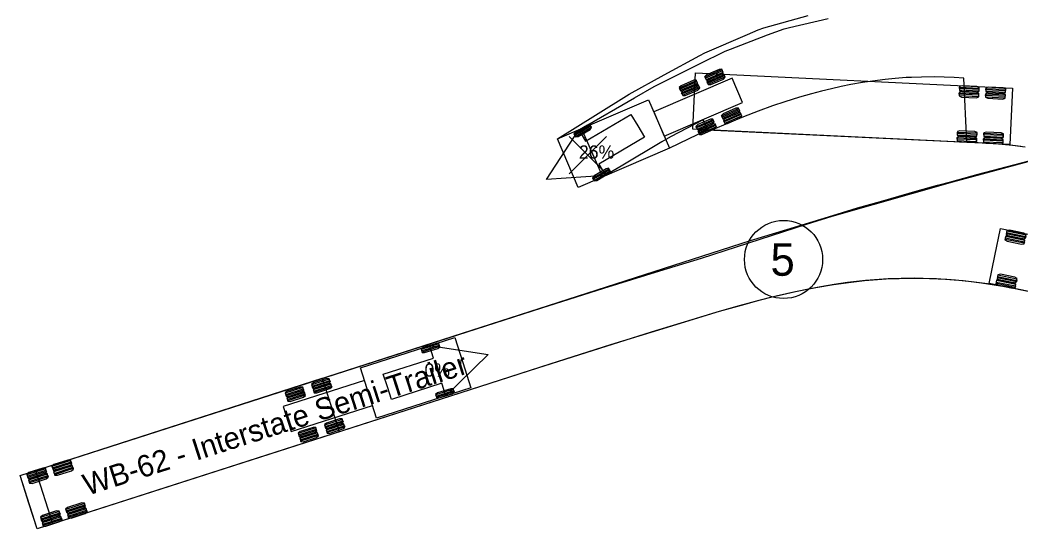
# Model space of a CAD drawing. Extents: x 1475900 to 1484331, y 375914 to 383395.
# Drawn here: x 1478908 to 1479059.2, y 379897.6 to 379974.6 of the extents above; entities that cross this region are included whole.
import ezdxf

# ---------------------------------------------------------------- set-up
doc = ezdxf.new("R2010")
doc.units = 0
doc.layers.add('0 (Construction)', color=7, linetype='Continuous')
doc.layers.add('Default', color=7, linetype='Continuous')

# ---------------------------------------------------------------- blocks, each defined once
blk = doc.blocks.new('ATRPTH_2')
at = {"layer": '0 (Construction)'}
for p, q in [((375809.142, 96492.838), (375810.582, 96494.277)), ((375810.582, 96492.838), (375809.142, 96494.277))]:
    blk.add_line(p, q, dxfattribs=at)
blk.add_lwpolyline([(375811.777, 96494.685), (375812.035, 96494.247), (375810.284, 96493.216), (375810.542, 96492.778), (375808.276, 96492.622), (375809.511, 96494.529), (375809.769, 96494.091), (375811.52, 96495.123), (375811.777, 96494.685)], dxfattribs=at)
at = {"layer": 'Default'}
for points in [[(375826.668, 96493.866), (375826.173, 96493.928), (375825.511, 96493.99), (375825.017, 96494.022), (375814.438, 96494.515), (375813.717, 96494.174), (375812.995, 96493.82), (375809.493, 96492.32), (375808.692, 96494.187), (375810.159, 96495.095), (375811.456, 96495.904), (375812.799, 96496.638), (375814.161, 96497.391), (375814.361, 96497.487), (375815.993, 96498.196), (375816.407, 96498.377), (375816.618, 96498.442), (375818.325, 96498.922)], [(375826.5, 96493.894), (375825.988, 96493.953), (375825.47, 96493.999), (375825.123, 96494.023), (375824.598, 96494.046), (375824.422, 96494.051), (375824.314, 96496.52), (375823.935, 96496.542), (375823.552, 96496.555), (375823.165, 96496.56), (375822.677, 96496.556), (375822.292, 96496.544), (375822.098, 96496.535), (375821.666, 96496.504), (375821.285, 96496.465), (375820.796, 96496.404), (375820.418, 96496.348), (375819.973, 96496.272), (375819.597, 96496.195), (375819.219, 96496.11), (375818.839, 96496.016), (375818.459, 96495.915), (375817.999, 96495.785), (375817.437, 96495.611), (375816.962, 96495.451), (375816.402, 96495.249), (375815.842, 96495.032), (375815.225, 96494.78), (375814.673, 96494.542), (375814.489, 96494.461), (375814.288, 96494.911), (375813.039, 96494.265), (375812.699, 96494.065), (375811.139, 96493.139), (375810.439, 96492.726), (375809.615, 96494.582), (375811.655, 96495.764), (375812.412, 96496.195), (375814.154, 96497.062), (375815.14, 96497.546), (375815.344, 96497.632), (375816.771, 96498.174), (375817.4, 96498.407), (375817.612, 96498.462), (375819.096, 96498.808)], [(375814.402, 96496.469), (375815.056, 96496.749), (375815.036, 96496.796), (375814.382, 96496.515), (375814.362, 96496.562), (375815.016, 96496.842), (375815.009, 96496.858), (375814.914, 96496.854), (375814.424, 96496.644), (375814.355, 96496.578), (375814.409, 96496.453), (375814.504, 96496.457), (375814.994, 96496.667), (375815.062, 96496.733), (375815.009, 96496.858)], [(375812.795, 96494.287), (375815.806, 96495.578), (375815.406, 96496.512), (375812.394, 96495.221), (375812.795, 96494.287)], [(375813.422, 96496.048), (375814.075, 96496.329), (375814.055, 96496.375), (375813.402, 96496.095), (375813.382, 96496.142), (375814.035, 96496.422), (375814.029, 96496.438), (375813.934, 96496.434), (375813.443, 96496.223), (375813.375, 96496.157), (375813.428, 96496.033), (375813.523, 96496.037), (375814.014, 96496.247), (375814.082, 96496.313), (375814.029, 96496.438)], [(375813.996, 96496.714), (375826.174, 96496.129), (375826.123, 96495.05), (375826.071, 96493.972), (375813.893, 96494.557), (375813.945, 96495.635), (375813.996, 96496.714), (375813.996, 96496.714)], [(375814.482, 96496.282), (375815.136, 96496.562), (375815.116, 96496.609), (375814.462, 96496.329), (375814.442, 96496.375), (375815.096, 96496.655), (375815.089, 96496.671), (375814.994, 96496.667), (375814.504, 96496.457), (375814.435, 96496.391), (375814.489, 96496.266), (375814.584, 96496.27), (375815.074, 96496.48), (375815.143, 96496.547), (375815.089, 96496.671)], [(375813.502, 96495.862), (375814.155, 96496.142), (375814.135, 96496.188), (375813.482, 96495.908), (375813.462, 96495.955), (375814.115, 96496.235), (375814.109, 96496.251), (375814.014, 96496.247), (375813.523, 96496.037), (375813.455, 96495.971), (375813.508, 96495.846), (375813.603, 96495.85), (375814.094, 96496.06), (375814.162, 96496.126), (375814.109, 96496.251)], [(375824.14, 96496.064), (375824.895, 96496.028), (375824.897, 96496.082), (375824.143, 96496.118), (375824.145, 96496.172), (375824.9, 96496.136), (375824.901, 96496.154), (375824.808, 96496.194), (375824.242, 96496.221), (375824.146, 96496.19), (375824.139, 96496.046), (375824.232, 96496.006), (375824.798, 96495.979), (375824.894, 96496.01), (375824.901, 96496.154)], [(375825.155, 96496.015), (375825.91, 96495.979), (375825.912, 96496.033), (375825.158, 96496.069), (375825.16, 96496.123), (375825.915, 96496.087), (375825.916, 96496.105), (375825.823, 96496.145), (375825.257, 96496.173), (375825.161, 96496.141), (375825.154, 96495.997), (375825.247, 96495.957), (375825.813, 96495.93), (375825.909, 96495.961), (375825.916, 96496.105)], [(375808.692, 96494.187), (375812.194, 96495.688), (375812.995, 96493.82), (375809.493, 96492.32), (375809.093, 96493.253), (375808.692, 96494.187), (375808.692, 96494.187)], [(375824.13, 96495.849), (375824.885, 96495.812), (375824.887, 96495.866), (375824.132, 96495.902), (375824.135, 96495.956), (375824.89, 96495.92), (375824.891, 96495.938), (375824.798, 96495.979), (375824.232, 96496.006), (375824.136, 96495.974), (375824.129, 96495.831), (375824.221, 96495.79), (375824.788, 96495.763), (375824.884, 96495.794), (375824.891, 96495.938)], [(375825.145, 96495.8), (375825.899, 96495.764), (375825.902, 96495.817), (375825.147, 96495.854), (375825.15, 96495.908), (375825.905, 96495.871), (375825.905, 96495.889), (375825.813, 96495.93), (375825.247, 96495.957), (375825.151, 96495.926), (375825.144, 96495.782), (375825.236, 96495.741), (375825.802, 96495.714), (375825.898, 96495.746), (375825.905, 96495.889)], [(375815.043, 96494.975), (375815.696, 96495.255), (375815.676, 96495.301), (375815.023, 96495.021), (375815.003, 96495.068), (375815.656, 96495.348), (375815.65, 96495.364), (375815.554, 96495.36), (375815.064, 96495.15), (375814.996, 96495.083), (375815.049, 96494.959), (375815.144, 96494.963), (375815.635, 96495.173), (375815.703, 96495.239), (375815.65, 96495.364)], [(375814.062, 96494.554), (375814.716, 96494.834), (375814.696, 96494.881), (375814.042, 96494.601), (375814.022, 96494.648), (375814.676, 96494.928), (375814.669, 96494.943), (375814.574, 96494.939), (375814.084, 96494.729), (375814.015, 96494.663), (375814.069, 96494.539), (375814.164, 96494.543), (375814.654, 96494.753), (375814.722, 96494.819), (375814.669, 96494.943)], [(375815.123, 96494.788), (375815.776, 96495.068), (375815.756, 96495.115), (375815.103, 96494.834), (375815.083, 96494.881), (375815.736, 96495.161), (375815.73, 96495.177), (375815.635, 96495.173), (375815.144, 96494.963), (375815.076, 96494.897), (375815.129, 96494.772), (375815.224, 96494.776), (375815.715, 96494.986), (375815.783, 96495.052), (375815.73, 96495.177)], [(375809.385, 96494.271), (375809.999, 96494.63), (375809.973, 96494.674), (375809.359, 96494.314), (375809.334, 96494.358), (375809.948, 96494.717), (375809.939, 96494.732), (375809.845, 96494.716), (375809.385, 96494.447), (375809.325, 96494.373), (375809.394, 96494.256), (375809.487, 96494.272), (375809.948, 96494.541), (375810.007, 96494.615), (375809.939, 96494.732)], [(375814.142, 96494.367), (375814.796, 96494.648), (375814.776, 96494.694), (375814.122, 96494.414), (375814.102, 96494.461), (375814.756, 96494.741), (375814.749, 96494.757), (375814.654, 96494.753), (375814.164, 96494.543), (375814.095, 96494.476), (375814.149, 96494.352), (375814.244, 96494.356), (375814.734, 96494.566), (375814.802, 96494.632), (375814.749, 96494.757)], [(375824.057, 96494.339), (375824.812, 96494.303), (375824.815, 96494.357), (375824.06, 96494.393), (375824.062, 96494.447), (375824.817, 96494.411), (375824.818, 96494.428), (375824.725, 96494.469), (375824.159, 96494.496), (375824.063, 96494.465), (375824.056, 96494.321), (375824.149, 96494.281), (375824.715, 96494.253), (375824.811, 96494.285), (375824.818, 96494.428)], [(375824.047, 96494.123), (375824.802, 96494.087), (375824.804, 96494.141), (375824.049, 96494.177), (375824.052, 96494.231), (375824.807, 96494.195), (375824.808, 96494.213), (375824.715, 96494.253), (375824.149, 96494.281), (375824.053, 96494.249), (375824.046, 96494.105), (375824.139, 96494.065), (375824.705, 96494.038), (375824.801, 96494.069), (375824.808, 96494.213)], [(375825.062, 96494.075), (375825.816, 96494.038), (375825.819, 96494.092), (375825.064, 96494.128), (375825.067, 96494.182), (375825.822, 96494.146), (375825.823, 96494.164), (375825.73, 96494.205), (375825.164, 96494.232), (375825.068, 96494.2), (375825.061, 96494.057), (375825.153, 96494.016), (375825.72, 96493.989), (375825.816, 96494.02), (375825.823, 96494.164)], [(375825.072, 96494.29), (375825.827, 96494.254), (375825.829, 96494.308), (375825.075, 96494.344), (375825.077, 96494.398), (375825.832, 96494.362), (375825.833, 96494.38), (375825.74, 96494.42), (375825.174, 96494.447), (375825.078, 96494.416), (375825.071, 96494.272), (375825.164, 96494.232), (375825.73, 96494.205), (375825.826, 96494.236), (375825.833, 96494.38)], [(375810.107, 96492.588), (375810.718, 96492.951), (375810.693, 96492.995), (375810.081, 96492.632), (375810.055, 96492.675), (375810.667, 96493.038), (375810.658, 96493.053), (375810.564, 96493.037), (375810.105, 96492.764), (375810.046, 96492.69), (375810.115, 96492.573), (375810.209, 96492.59), (375810.668, 96492.862), (375810.727, 96492.936), (375810.658, 96493.053)]]:
    blk.add_lwpolyline(points, dxfattribs=at)
at = {"layer": '0 (Construction)'}
blk.add_text('26%', height=0.508, dxfattribs=at).set_placement((375809.518, 96493.425))
blk = doc.blocks.new('ATRPTH_5')
at = {"layer": '0 (Construction)'}
blk.add_lwpolyline([(375802.159, 96484.658), (375802.003, 96485.142), (375803.938, 96485.763), (375803.782, 96486.247), (375806.028, 96485.902), (375804.404, 96484.313), (375804.249, 96484.796), (375802.314, 96484.174), (375802.159, 96484.658)], dxfattribs=at)
blk.add_circle((375817.382, 96489.551), 1.5, dxfattribs=at)
at = {"layer": 'Default'}
for points in [[(375788.045, 96481.255), (375816.115, 96490.274), (375817.509, 96490.706), (375819.106, 96491.189), (375820.021, 96491.467), (375820.221, 96491.529), (375821.108, 96491.779), (375822.513, 96492.181), (375823.299, 96492.399), (375823.849, 96492.547), (375824.855, 96492.829), (375827.891, 96493.626), (375828.093, 96493.68), (375828.309, 96493.696), (375831.41, 96493.128), (375831.842, 96493.051)], [(375788.649, 96481.449), (375808.09, 96487.694), (375810.477, 96488.449), (375812.624, 96489.117), (375814.229, 96489.606), (375818.261, 96490.901), (375819.254, 96491.219), (375823.883, 96492.539), (375827.117, 96493.403), (375827.346, 96493.429), (375827.811, 96493.377), (375828.906, 96493.24), (375830.205, 96493.068), (375830.85, 96492.98), (375831.083, 96492.886)], [(375826.898, 96488.298), (375826.372, 96488.413), (375826.023, 96488.482), (375825.326, 96488.599), (375824.806, 96488.672), (375824.289, 96488.73), (375823.774, 96488.775), (375823.261, 96488.805), (375822.75, 96488.822), (375822.411, 96488.827), (375821.904, 96488.82), (375821.399, 96488.801), (375820.879, 96488.767), (375820.531, 96488.737), (375819.84, 96488.661), (375819.326, 96488.589), (375818.818, 96488.506), (375818.334, 96488.415), (375817.841, 96488.313), (375817.341, 96488.199), (375816.834, 96488.076), (375816.285, 96487.934), (375815.53, 96487.728), (375814.782, 96487.513), (375813.859, 96487.237), (375812.29, 96486.753), (375810.307, 96486.132), (375807.928, 96485.377), (375804.582, 96484.303), (375789.31, 96479.394), (375788.649, 96481.449)], [(375836.688, 96486.26), (375826.126, 96488.456), (375825.476, 96488.57), (375824.982, 96488.643), (375824.488, 96488.704), (375823.991, 96488.751), (375823.66, 96488.777), (375822.995, 96488.81), (375822.496, 96488.819), (375821.82, 96488.811), (375821.321, 96488.79), (375820.828, 96488.757), (375820.494, 96488.726), (375819.986, 96488.669), (375819.307, 96488.579), (375818.627, 96488.465), (375818.288, 96488.401), (375817.782, 96488.296), (375817.102, 96488.139), (375816.428, 96487.969), (375815.757, 96487.788), (375814.913, 96487.55), (375814.075, 96487.301), (375812.737, 96486.891), (375810.733, 96486.266), (375808.402, 96485.528), (375805.736, 96484.674), (375788.705, 96479.2), (375788.045, 96481.255)], [(375837.223, 96486.172), (375825.281, 96488.632), (375825.499, 96489.689), (375825.717, 96490.746), (375837.658, 96488.287), (375837.44, 96487.23), (375837.223, 96486.172), (375837.223, 96486.172)], [(375826.698, 96490.489), (375825.958, 96490.641), (375825.947, 96490.589), (375826.687, 96490.436), (375826.676, 96490.383), (375825.936, 96490.536), (375825.932, 96490.518), (375826.018, 96490.464), (375826.573, 96490.349), (375826.673, 96490.366), (375826.702, 96490.507), (375826.616, 96490.561), (375826.061, 96490.675), (375825.961, 96490.659), (375825.932, 96490.518)], [(375826.654, 96490.277), (375825.914, 96490.43), (375825.903, 96490.377), (375826.644, 96490.225), (375826.633, 96490.172), (375825.893, 96490.324), (375825.889, 96490.307), (375825.974, 96490.252), (375826.529, 96490.138), (375826.629, 96490.154), (375826.658, 96490.295), (375826.573, 96490.349), (375826.018, 96490.464), (375825.918, 96490.448), (375825.889, 96490.307)], [(375826.306, 96488.586), (375825.566, 96488.738), (375825.555, 96488.685), (375826.295, 96488.533), (375826.284, 96488.48), (375825.544, 96488.632), (375825.54, 96488.615), (375825.626, 96488.561), (375826.181, 96488.446), (375826.281, 96488.462), (375826.31, 96488.603), (375826.224, 96488.658), (375825.669, 96488.772), (375825.57, 96488.756), (375825.54, 96488.615)], [(375826.35, 96488.797), (375825.609, 96488.95), (375825.599, 96488.897), (375826.339, 96488.744), (375826.328, 96488.692), (375825.588, 96488.844), (375825.584, 96488.826), (375825.669, 96488.772), (375826.224, 96488.658), (375826.324, 96488.674), (375826.353, 96488.815), (375826.268, 96488.869), (375825.713, 96488.983), (375825.613, 96488.967), (375825.584, 96488.826)], [(375805.371, 96484.623), (375801.744, 96483.458), (375801.122, 96485.392), (375804.749, 96486.558), (375805.06, 96485.591), (375805.371, 96484.623), (375805.371, 96484.623)], [(375804.136, 96486.308), (375803.459, 96486.09), (375803.475, 96486.042), (375804.152, 96486.259), (375804.167, 96486.211), (375803.49, 96485.993), (375803.495, 96485.977), (375803.59, 96485.972), (375804.098, 96486.135), (375804.173, 96486.195), (375804.131, 96486.324), (375804.036, 96486.329), (375803.528, 96486.165), (375803.454, 96486.106), (375803.495, 96485.977)], [(375800.313, 96482.931), (375788.705, 96479.2), (375788.375, 96480.227), (375788.045, 96481.255), (375799.652, 96484.986), (375799.982, 96483.958), (375800.313, 96482.931), (375800.313, 96482.931)], [(375801.278, 96484.908), (375798.158, 96483.906), (375798.469, 96482.938), (375801.589, 96483.941), (375801.278, 96484.908)], [(375799.929, 96484.955), (375799.252, 96484.737), (375799.267, 96484.689), (375799.944, 96484.907), (375799.96, 96484.858), (375799.283, 96484.641), (375799.288, 96484.625), (375799.383, 96484.62), (375799.891, 96484.783), (375799.965, 96484.842), (375799.924, 96484.971), (375799.829, 96484.976), (375799.321, 96484.813), (375799.246, 96484.754), (375799.288, 96484.625)], [(375798.913, 96484.629), (375798.236, 96484.411), (375798.252, 96484.363), (375798.929, 96484.58), (375798.944, 96484.532), (375798.267, 96484.314), (375798.272, 96484.298), (375798.367, 96484.293), (375798.875, 96484.456), (375798.949, 96484.516), (375798.908, 96484.645), (375798.813, 96484.65), (375798.305, 96484.487), (375798.231, 96484.427), (375798.272, 96484.298)], [(375799.991, 96484.762), (375799.314, 96484.544), (375799.329, 96484.496), (375800.006, 96484.713), (375800.022, 96484.665), (375799.345, 96484.447), (375799.35, 96484.431), (375799.445, 96484.426), (375799.953, 96484.589), (375800.027, 96484.649), (375799.986, 96484.778), (375799.891, 96484.783), (375799.383, 96484.62), (375799.309, 96484.56), (375799.35, 96484.431)], [(375804.696, 96484.566), (375804.019, 96484.349), (375804.034, 96484.3), (375804.711, 96484.518), (375804.727, 96484.47), (375804.05, 96484.252), (375804.055, 96484.236), (375804.15, 96484.231), (375804.658, 96484.394), (375804.732, 96484.454), (375804.691, 96484.583), (375804.596, 96484.588), (375804.088, 96484.424), (375804.014, 96484.365), (375804.055, 96484.236)], [(375798.975, 96484.435), (375798.298, 96484.218), (375798.314, 96484.169), (375798.991, 96484.387), (375799.006, 96484.338), (375798.329, 96484.121), (375798.334, 96484.105), (375798.429, 96484.1), (375798.937, 96484.263), (375799.012, 96484.322), (375798.97, 96484.451), (375798.875, 96484.456), (375798.367, 96484.293), (375798.293, 96484.234), (375798.334, 96484.105)], [(375800.426, 96483.407), (375799.749, 96483.19), (375799.765, 96483.141), (375800.442, 96483.359), (375800.457, 96483.311), (375799.78, 96483.093), (375799.785, 96483.077), (375799.88, 96483.072), (375800.388, 96483.235), (375800.462, 96483.295), (375800.421, 96483.424), (375800.326, 96483.429), (375799.818, 96483.265), (375799.744, 96483.206), (375799.785, 96483.077)], [(375799.411, 96483.081), (375798.733, 96482.863), (375798.749, 96482.815), (375799.426, 96483.033), (375799.442, 96482.984), (375798.765, 96482.767), (375798.77, 96482.751), (375798.865, 96482.745), (375799.373, 96482.909), (375799.447, 96482.968), (375799.405, 96483.097), (375799.31, 96483.102), (375798.803, 96482.939), (375798.728, 96482.879), (375798.77, 96482.751)], [(375800.488, 96483.214), (375799.811, 96482.996), (375799.827, 96482.948), (375800.504, 96483.166), (375800.519, 96483.117), (375799.842, 96482.9), (375799.848, 96482.884), (375799.943, 96482.878), (375800.45, 96483.042), (375800.525, 96483.101), (375800.483, 96483.23), (375800.388, 96483.235), (375799.88, 96483.072), (375799.806, 96483.012), (375799.848, 96482.884)], [(375799.473, 96482.888), (375798.796, 96482.67), (375798.811, 96482.622), (375799.488, 96482.839), (375799.504, 96482.791), (375798.827, 96482.573), (375798.832, 96482.557), (375798.927, 96482.552), (375799.435, 96482.715), (375799.509, 96482.775), (375799.468, 96482.904), (375799.373, 96482.909), (375798.865, 96482.745), (375798.79, 96482.686), (375798.832, 96482.557)], [(375789.993, 96481.825), (375789.273, 96481.593), (375789.29, 96481.542), (375790.009, 96481.773), (375790.026, 96481.722), (375789.307, 96481.491), (375789.312, 96481.474), (375789.413, 96481.468), (375789.953, 96481.642), (375790.031, 96481.705), (375789.987, 96481.842), (375789.886, 96481.847), (375789.347, 96481.674), (375789.268, 96481.611), (375789.312, 96481.474)], [(375789.026, 96481.514), (375788.306, 96481.282), (375788.323, 96481.231), (375789.042, 96481.462), (375789.059, 96481.411), (375788.339, 96481.18), (375788.345, 96481.163), (375788.446, 96481.157), (375788.985, 96481.331), (375789.064, 96481.394), (375789.02, 96481.531), (375788.919, 96481.536), (375788.38, 96481.363), (375788.301, 96481.3), (375788.345, 96481.163)], [(375790.059, 96481.619), (375789.34, 96481.388), (375789.356, 96481.336), (375790.075, 96481.568), (375790.092, 96481.516), (375789.373, 96481.285), (375789.378, 96481.268), (375789.479, 96481.263), (375790.019, 96481.436), (375790.097, 96481.499), (375790.053, 96481.636), (375789.953, 96481.642), (375789.413, 96481.468), (375789.334, 96481.405), (375789.378, 96481.268)], [(375789.092, 96481.308), (375788.372, 96481.077), (375788.389, 96481.026), (375789.108, 96481.257), (375789.125, 96481.205), (375788.405, 96480.974), (375788.411, 96480.957), (375788.512, 96480.952), (375789.051, 96481.125), (375789.13, 96481.188), (375789.086, 96481.325), (375788.985, 96481.331), (375788.446, 96481.157), (375788.367, 96481.094), (375788.411, 96480.957)], [(375790.521, 96480.18), (375789.802, 96479.949), (375789.819, 96479.898), (375790.538, 96480.129), (375790.554, 96480.078), (375789.835, 96479.846), (375789.841, 96479.829), (375789.942, 96479.824), (375790.481, 96479.997), (375790.56, 96480.06), (375790.516, 96480.197), (375790.415, 96480.203), (375789.875, 96480.029), (375789.797, 96479.966), (375789.841, 96479.829)], [(375790.588, 96479.975), (375789.868, 96479.744), (375789.885, 96479.692), (375790.604, 96479.923), (375790.621, 96479.872), (375789.901, 96479.641), (375789.907, 96479.624), (375790.008, 96479.618), (375790.547, 96479.792), (375790.626, 96479.855), (375790.582, 96479.992), (375790.481, 96479.997), (375789.942, 96479.824), (375789.863, 96479.761), (375789.907, 96479.624)], [(375789.554, 96479.869), (375788.835, 96479.638), (375788.851, 96479.587), (375789.571, 96479.818), (375789.587, 96479.767), (375788.868, 96479.535), (375788.873, 96479.518), (375788.974, 96479.513), (375789.514, 96479.686), (375789.593, 96479.749), (375789.549, 96479.887), (375789.448, 96479.892), (375788.908, 96479.718), (375788.829, 96479.655), (375788.873, 96479.518)], [(375789.62, 96479.664), (375788.901, 96479.433), (375788.917, 96479.381), (375789.637, 96479.612), (375789.653, 96479.561), (375788.934, 96479.33), (375788.939, 96479.313), (375789.04, 96479.307), (375789.58, 96479.481), (375789.659, 96479.544), (375789.615, 96479.681), (375789.514, 96479.686), (375788.974, 96479.513), (375788.895, 96479.45), (375788.939, 96479.313)]]:
    blk.add_lwpolyline(points, dxfattribs=at)
at = {"layer": '0 (Construction)'}
for s, height, p in [('5', 1.25, (375816.882, 96488.926)), ('0%', 0.508, (375803.585, 96485.051))]:
    blk.add_text(s, height=height, dxfattribs=at).set_placement(p)
at = {"layer": 'Default'}
blk.add_text('WB-62 - Interstate Semi-Trailer', height=0.83333, rotation=17.8196, dxfattribs=at).set_placement((375790.63, 96480.471))

msp = doc.modelspace()

# ---------------------------------------------------------------- block references
at = {"layer": 'Default', "xscale": 3.937007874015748, "yscale": 3.937007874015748}
for name in ['ATRPTH_2', 'ATRPTH_5']:
    msp.add_blockref(name, (-572.52, 58.24), dxfattribs=at)

doc.saveas('drawing.dxf')
